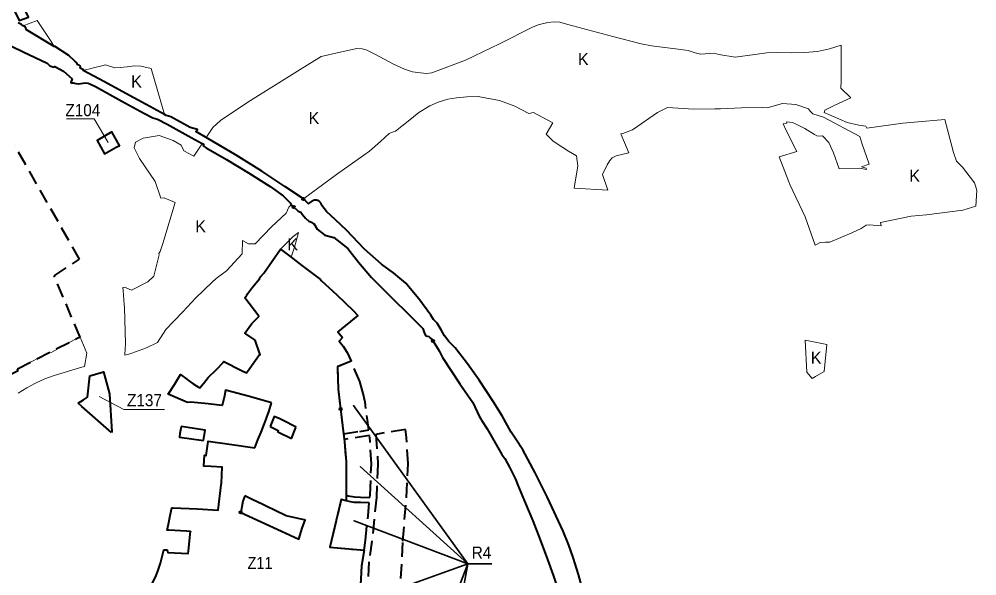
# Model space of a CAD drawing. Extents: x -650276 to -642489, y -1074311 to -1066658.
# Drawn here: x -646145 to -644241, y -1069915 to -1068808 of the extents above; entities that cross this region are included whole.
import ezdxf

# ---------------------------------------------------------------- set-up
doc = ezdxf.new("R2010")
doc.units = 0
doc.header["$LTSCALE"] = 9.6
doc.header["$PDMODE"] = 32
doc.header["$PDSIZE"] = 4.8
doc.linetypes.add('MEDIUM_DASHED', pattern=[4.5, 3, -1.5])
for name, color, linetype, lineweight in [('4', 7, 'Continuous', 40), ('44', 7, 'Continuous', 40), ('45', 7, 'Continuous', 40), ('46', 7, 'Continuous', 13), ('47', 7, 'Continuous', 13), ('48', 7, 'Continuous', 35), ('57', 7, 'Continuous', 35), ('59', 7, 'Continuous', 13), ('61', 7, 'MEDIUM_DASHED', 40), ('62', 7, 'Continuous', 35)]:
    doc.layers.add(name, color=color, linetype=linetype, lineweight=lineweight)

msp = doc.modelspace()

# ---------------------------------------------------------------- linework, layer by layer
at = {"layer": '4'}
for points in [[(-646004.7, -1069517.16), (-645977.73, -1069509.11), (-645965.36, -1069552.99), (-645960.78, -1069628.91), (-645961.36, -1069630.05)], [(-646027.49, -1069571.79), (-646017.39, -1069564.94), (-646009.52, -1069559.6), (-646004.7, -1069517.16)], [(-645961.36, -1069630.05), (-646020.4, -1069578.04), (-646027.49, -1069571.79)]]:
    msp.add_lwpolyline(points, dxfattribs=at)
at = {"layer": '44'}
for points in [[(-646305.678, -1068613.404), (-646243.997, -1068647.407), (-646236.707, -1068651.891), (-646228.691, -1068658.051), (-646221.348, -1068665.144), (-646213.659, -1068674.696), (-646209.179, -1068681.795), (-646204.654, -1068690.937), (-646145.083, -1068810.83), (-646126.317, -1068803.654), (-646186.371, -1068682.825)], [(-645579.94, -1069165.52), (-645616.63, -1069140.8), (-645662.44, -1069109.89), (-645713.61, -1069078.06), (-645770.04, -1069045.34), (-645773.38, -1069043.46), (-645793.638, -1069031.021), (-645790.53, -1069027.19), (-645805.16, -1069023.52), (-645843.56, -1069002.41), (-645848.18, -1069000.48), (-645852.91, -1068999.62), (-645856.26, -1068997.79), (-645892.77, -1068977.86), (-645933.28, -1068955.74), (-645975.31, -1068932.8), (-646017.55, -1068909.75), (-646017.39, -1068908.42), (-646023.56, -1068905.05), (-646023.13, -1068903.12), (-646023.92, -1068900.73), (-646025.57, -1068899.39), (-646028.18, -1068898.89), (-646031.31, -1068894.32), (-646034.65, -1068891.12), (-646046.48, -1068879.92), (-646074.78, -1068861.51), (-646075.56, -1068861.95), (-646130.68, -1068829.21), (-646132.62, -1068823.54), (-646136.99, -1068820.88), (-646140.73, -1068818.61), (-646146.85, -1068814.88)], [(-646182.57, -1068851.3), (-646137.23, -1068872.6), (-646089.63, -1068895.5), (-646084.1, -1068900.51), (-646076.09, -1068903.48), (-646074.51, -1068901.9), (-646057.13, -1068911.62), (-646039.84, -1068926.67), (-646042.5, -1068933.91), (-646040.65, -1068934.59), (-646037.5, -1068934.7), (-646032.61, -1068936.1)], [(-646032.61, -1068936.1), (-646027.69, -1068936.6), (-646022.77, -1068936.12), (-646017.6, -1068934.89), (-646012.64, -1068934.34), (-646007.7, -1068935.18), (-646002.95, -1068936.95), (-645993.5, -1068942.1), (-645940.77, -1068970.74), (-645896.91, -1068994.75), (-645879.17, -1069004.02), (-645874.49, -1069005.73), (-645869.83, -1069006.45), (-645850.79, -1069016.84), (-645803.29, -1069042.92), (-645781.12, -1069055.29), (-645777.73, -1069057.2), (-645779.49, -1069059.92), (-645773.29, -1069063.99), (-645732.65, -1069086.82), (-645688.87, -1069113.44), (-645646.08, -1069140.37), (-645620.2, -1069159.26), (-645606.11, -1069172.98), (-645603.91, -1069176.86), (-645599, -1069181.48)], [(-645571.9, -1069173.43), (-645579.94, -1069165.52), (-645579.94, -1069165.52)], [(-645543.43, -1069178.39), (-645543.547, -1069177.727), (-645543.706, -1069177.053), (-645543.907, -1069176.37), (-645544.154, -1069175.682), (-645544.448, -1069174.993), (-645544.792, -1069174.308), (-645545.186, -1069173.63), (-645545.631, -1069172.966), (-645546.127, -1069172.32), (-645546.674, -1069171.699), (-645547.269, -1069171.107), (-645547.91, -1069170.551), (-645548.594, -1069170.034), (-645549.317, -1069169.563), (-645550.076, -1069169.141), (-645550.863, -1069168.772), (-645551.674, -1069168.459), (-645552.504, -1069168.203), (-645553.344, -1069168.007), (-645554.191, -1069167.87), (-645555.036, -1069167.793), (-645555.875, -1069167.772), (-645556.702, -1069167.808), (-645557.511, -1069167.896), (-645558.298, -1069168.035), (-645559.06, -1069168.219), (-645559.793, -1069168.445), (-645560.494, -1069168.709), (-645561.162, -1069169.007), (-645561.794, -1069169.334), (-645562.39, -1069169.686), (-645562.95, -1069170.06), (-645567.5, -1069173.46), (-645569.81, -1069175.03), (-645571.9, -1069173.43)], [(-645599, -1069181.48), (-645599, -1069181.48), (-645592.24, -1069187.73), (-645590.41, -1069189.45), (-645584.73, -1069191.88), (-645582.63, -1069195.88), (-645575.58, -1069203.57), (-645568.9, -1069209.87), (-645567.07, -1069210.45), (-645562.17, -1069212.02), (-645560.72, -1069214.25), (-645559.33, -1069214.54), (-645552.2, -1069225.59), (-645537.44, -1069237.41), (-645519.59, -1069242.38), (-645491.63, -1069264.25), (-645470.44, -1069291.24), (-645444.62, -1069321.35), (-645405.7, -1069360.27), (-645368.13, -1069397.37), (-645358.04, -1069406.84), (-645342.49, -1069423.06), (-645339.31, -1069433.27), (-645336.66, -1069437.47), (-645330.57, -1069438.89), (-645327.2, -1069442.53), (-645323.36, -1069445.79), (-645322.13, -1069447.96)], [(-645024.45, -1069944.43), (-645032.85, -1069912.07), (-645043.5, -1069878.37), (-645051.78, -1069854.2), (-645063.26, -1069825.99), (-645095.1, -1069757.62), (-645118.98, -1069710.08), (-645143.56, -1069664.05), (-645148.8, -1069656.1), (-645150.3, -1069653.84), (-645153.33, -1069649.24), (-645166.67, -1069629), (-645184.88, -1069596.58), (-645202.56, -1069568.23), (-645230.1, -1069525.98), (-645253.4, -1069493.06), (-645278.31, -1069461.33), (-645281.4, -1069458.4), (-645290.5, -1069449.03), (-645299.61, -1069437.97), (-645306.16, -1069425.55), (-645314.14, -1069412.54), (-645321.1, -1069405.21), (-645326.59, -1069396.64), (-645350.63, -1069363.98), (-645371.12, -1069339.47), (-645376.38, -1069332.65), (-645400.07, -1069313.32), (-645424.8, -1069295.24), (-645458.45, -1069265.56), (-645494.13, -1069227.63), (-645515.89, -1069206.66), (-645534.25, -1069190.56), (-645543.43, -1069178.39)], [(-645322.13, -1069447.96), (-645309.62, -1069467.79), (-645303.57, -1069480.49), (-645268.57, -1069533.23), (-645242.75, -1069570.26), (-645230.42, -1069597.39), (-645227.27, -1069602.68), (-645225.7, -1069605.32), (-645214.76, -1069622.37), (-645198.41, -1069650.49), (-645185.17, -1069673.38), (-645179.12, -1069681.3), (-645170.3, -1069698.91), (-645158.43, -1069722.61), (-645153.44, -1069734.71), (-645140.27, -1069766.68), (-645123.84, -1069805.38), (-645108.74, -1069843.58), (-645094.42, -1069882.65), (-645083.31, -1069913.37), (-645071.53, -1069948.89)]]:
    msp.add_lwpolyline(points, dxfattribs=at)
for p in [(-645579.94, -1069165.52), (-645599, -1069181.48), (-645322.13, -1069447.96)]:
    msp.add_point(p, dxfattribs=at)
at = {"layer": '45'}
msp.add_line((-645704.355, -1069788.786), (-645623.75, -1069825.97), dxfattribs=at)
for points in [[(-645944.69, -1069060.7), (-645960.67, -1069032.26), (-645990.13, -1069049.3), (-645975.48, -1069075.71), (-645952.21, -1069062.4)], [(-645944.69, -1069060.7), (-645960.67, -1069032.26), (-645990.13, -1069049.3), (-645975.48, -1069075.71), (-645952.21, -1069062.4)], [(-645952.21, -1069062.4), (-645946.84, -1069059.58), (-645944.69, -1069060.7)], [(-645952.21, -1069062.4), (-645946.84, -1069059.58), (-645944.69, -1069060.7)], [(-645668.722, -1069398.75), (-645696.19, -1069362.01), (-645692.38, -1069356.67), (-645690.81, -1069354.28), (-645687.22, -1069349), (-645680.8, -1069341.08), (-645667, -1069324.06), (-645664.89, -1069320.2), (-645658.9, -1069312.83), (-645625.11, -1069265.42), (-645604.114, -1069281.49), (-645594.94, -1069288.511)], [(-645594.94, -1069288.511), (-645583.13, -1069297.55), (-645546.19, -1069325.81), (-645544.26, -1069327.35), (-645513.41, -1069356.18), (-645480.72, -1069386.96), (-645471.738, -1069397.026), (-645511.464, -1069429.794), (-645501.878, -1069440.838)], [(-645675.91, -1069446.56), (-645694.21, -1069433.78), (-645696.45, -1069432.21), (-645682.28, -1069412.88), (-645678.06, -1069408.54), (-645668.61, -1069398.9), (-645668.722, -1069398.75)], [(-645501.878, -1069440.838), (-645508.994, -1069447.955), (-645501, -1069458), (-645493, -1069471), (-645484.783, -1069488.256), (-645512, -1069499), (-645511, -1069544), (-645506, -1069583)], [(-645786.388, -1069541.673), (-645779.376, -1069532.962), (-645778.754, -1069532.198), (-645769.369, -1069520.672), (-645768.995, -1069520.305), (-645752.715, -1069504.328), (-645738.986, -1069489.868), (-645737.897, -1069488.534), (-645702.82, -1069506.64), (-645692.87, -1069511.229), (-645690.84, -1069508.32), (-645667.31, -1069474.6), (-645665.58, -1069475.61), (-645675.91, -1069446.56)], [(-645836.44, -1069534.5), (-645824.05, -1069514.34), (-645811.75, -1069523.81), (-645808.1, -1069526.61), (-645799.07, -1069532.8), (-645790.62, -1069538.59), (-645786.388, -1069541.673)], [(-645810.08, -1069570.39), (-645848.78, -1069553.91), (-645836.44, -1069534.5)], [(-645643.16, -1069570.6), (-645687.29, -1069558.04), (-645734.5, -1069545.89), (-645736.8, -1069556.91), (-645741.14, -1069576.19), (-645769.04, -1069573), (-645803.513, -1069569.263), (-645810.08, -1069570.39)], [(-645676.34, -1069660.28), (-645670.23, -1069644.67), (-645664.19, -1069629.24), (-645657.52, -1069612.2), (-645656.15, -1069608.71), (-645649.91, -1069592.39), (-645648.68, -1069589.06), (-645644.56, -1069575.61), (-645643.16, -1069570.6)], [(-645506, -1069583), (-645500.137, -1069632.833), (-645500.137, -1069632.833)], [(-645594.58, -1069619.56), (-645621.56, -1069605.68), (-645626.95, -1069602.91), (-645638.203, -1069597.8), (-645645.715, -1069618.085)], [(-645823.082, -1069618.279), (-645823.13, -1069618.452), (-645825.295, -1069632.053), (-645826.133, -1069638.843), (-645826.151, -1069639.057), (-645778.45, -1069645.92)], [(-645823.082, -1069618.279), (-645823.13, -1069618.452), (-645825.295, -1069632.053), (-645826.133, -1069638.843), (-645826.151, -1069639.057), (-645778.45, -1069645.92)], [(-645778.45, -1069645.92), (-645775.46, -1069625.13), (-645823.082, -1069618.279)], [(-645778.45, -1069645.92), (-645775.46, -1069625.13), (-645823.082, -1069618.279)], [(-645645.715, -1069618.085), (-645629.78, -1069626.03), (-645630.93, -1069628.84), (-645603.7, -1069641.75)], [(-645603.7, -1069641.75), (-645594.818, -1069620.139), (-645594.58, -1069619.56)], [(-645839.721, -1069780.247), (-645839.658, -1069779.835), (-645791.2, -1069781.92), (-645749.48, -1069784.61), (-645743.36, -1069733.7), (-645743.01, -1069730.72), (-645741.43, -1069698.68), (-645763.24, -1069697.58), (-645777.62, -1069696.85), (-645776.45, -1069675.26), (-645773.02, -1069675.47), (-645769.36, -1069648), (-645769.264, -1069647.213), (-645726.57, -1069653.22), (-645676.34, -1069660.28)], [(-645500.137, -1069632.833), (-645498, -1069648), (-645495, -1069688), (-645495, -1069744), (-645495, -1069766), (-645504.976, -1069763.332), (-645527, -1069858), (-645459.312, -1069864.01), (-645464.288, -1069895.362), (-645465.756, -1069921.035), (-645469.701, -1069990.011)], [(-645696.517, -1069756.039), (-645700.028, -1069766.286), (-645704.355, -1069788.786)], [(-645660.57, -1069773.31), (-645681.76, -1069763.13), (-645696.517, -1069756.039)], [(-645804.185, -1069825.84), (-645804.28, -1069826.76), (-645812.18, -1069826.3), (-645847.62, -1069824.26), (-645850.63, -1069824.09), (-645848.35, -1069812.09), (-645844.57, -1069795.07), (-645841.41, -1069779.76), (-645839.658, -1069779.835), (-645839.721, -1069780.247)], [(-645613.84, -1069795.78), (-645635.79, -1069785.23), (-645652.378, -1069777.251), (-645660.57, -1069773.31)], [(-645623.75, -1069825.97), (-645589.23, -1069841.89), (-645582.31, -1069820.05), (-645577.52, -1069807.26), (-645576.34, -1069804.13), (-645578.134, -1069803.731), (-645613.84, -1069795.78)], [(-645742.967, -1069941.862), (-645768.424, -1069948.431), (-645833, -1069966), (-645880.431, -1069930.3), (-645874.219, -1069917.496), (-645869.262, -1069905.935), (-645863.95, -1069889.468), (-645857.289, -1069863.338), (-645857.204, -1069862.954), (-645850.92, -1069863.41), (-645849.79, -1069868.4), (-645808.84, -1069870.75), (-645808.28, -1069865.39), (-645804.185, -1069825.84)]]:
    msp.add_lwpolyline(points, dxfattribs=at)
for p in [(-645506, -1069583), (-645704.355, -1069788.786)]:
    msp.add_point(p, dxfattribs=at)
at = {"layer": '46'}
msp.add_lwpolyline([(-646051.21, -1069006.26), (-645996.286, -1069006.26), (-645968.211, -1069053.466)], dxfattribs=at)
msp.add_lwpolyline([(-646051.21, -1069006.26), (-645996.286, -1069006.26), (-645968.211, -1069053.466)], dxfattribs=at)
at = {"layer": '47'}
for points in [[(-646075.56, -1068861.95), (-646130.68, -1068829.21), (-646132.62, -1068823.54), (-646136.99, -1068820.88), (-646109.35, -1068810.23)], [(-646109.35, -1068810.23), (-646081.72, -1068852.51), (-646075.56, -1068861.95)], [(-645239.85, -1068880.94), (-645190.22, -1068857.23), (-645124.36, -1068824.11), (-645112.77, -1068819.13), (-645093.56, -1068814.27), (-645081.12, -1068813.15), (-645070.05, -1068814), (-645053.97, -1068818.31), (-644964.45, -1068842.38), (-644908.26, -1068856.91), (-644887.91, -1068860.82), (-644834.84, -1068867.4), (-644814.47, -1068870.12), (-644800.87, -1068874.97), (-644790.41, -1068877.73), (-644763.04, -1068875.63), (-644753.71, -1068878.41), (-644721.29, -1068883.2), (-644681.99, -1068878.15), (-644658.39, -1068874.59), (-644636.55, -1068874.02), (-644608.71, -1068874.78), (-644583.26, -1068874.26), (-644557.75, -1068872.33), (-644533.84, -1068867.2), (-644510.62, -1068859.35), (-644510.567, -1068897.909), (-644510.75, -1068931.16), (-644511.47, -1068945.37), (-644491.31, -1068964.35), (-644523.4, -1068978.98), (-644543.05, -1068988.64), (-644544.02, -1068993.75), (-644498.28, -1069013.19), (-644475.09, -1069018.99), (-644461.74, -1069020.83), (-644459.67, -1069024.41), (-644387.91, -1069014.64), (-644364.53, -1069012.83), (-644304.6, -1069007.55), (-644286.94, -1069073.19)], [(-645544.33, -1068882.17), (-645500.83, -1068872.25), (-645473.89, -1068866.13), (-645462.97, -1068866.88), (-645455.34, -1068868.9), (-645436.72, -1068877.85), (-645400.92, -1068897.18), (-645379.06, -1068907.27), (-645362.84, -1068912.83), (-645352.46, -1068914.25), (-645335.45, -1068915.77)], [(-645426.3, -1069051.02), (-645448.49, -1069070.45), (-645459.5, -1069078.59), (-645514.08, -1069116.5), (-645579.94, -1069165.52), (-645616.63, -1069140.8), (-645662.44, -1069109.89), (-645694.447, -1069089.98), (-645713.61, -1069078.06), (-645770.04, -1069045.34), (-645773.38, -1069043.46), (-645760.07, -1069023.11), (-645744.65, -1069009.71), (-645690.34, -1068973.16), (-645586.28, -1068907.71), (-645544.33, -1068882.17)], [(-645335.45, -1068915.77), (-645324.79, -1068914.82), (-645257.5, -1068889.68), (-645239.85, -1068880.94)], [(-645973.36, -1068898.93), (-645980.93, -1068900.85), (-645994.9, -1068904.1), (-646004.88, -1068906.5), (-646010.48, -1068907.86), (-646017.55, -1068909.75), (-645975.31, -1068932.8), (-645933.28, -1068955.74)], [(-645882.63, -1068905.88), (-645902.91, -1068901.43), (-645915.61, -1068901.02), (-645930.1, -1068902.47), (-645944.23, -1068904.13), (-645954.59, -1068904.41), (-645973.36, -1068898.93)], [(-645933.28, -1068955.74), (-645892.77, -1068977.86), (-645856.26, -1068997.79), (-645882.63, -1068905.88)], [(-645131.73, -1068995.69), (-645159.37, -1068981.11), (-645189.84, -1068969.91), (-645229.27, -1068962.28), (-645232.4, -1068961.67), (-645255.21, -1068962.49), (-645275.45, -1068964.38), (-645292.77, -1068966.91), (-645311.99, -1068972.74), (-645328.55, -1068980.37), (-645350.17, -1068993.33), (-645371.35, -1069010.64), (-645396.53, -1069030.88)], [(-644473.222, -1069040.994), (-644545.54, -1069003.12), (-644567.09, -1068996.26), (-644572.05, -1068991.08), (-644575.29, -1068986.48), (-644600.67, -1068977.77), (-644627.41, -1068975.6), (-644657.61, -1068983.91), (-644667.57, -1068983.47), (-644708.6, -1068984.54), (-644750.67, -1068986.34), (-644761.88, -1068986.27), (-644803.31, -1068986.97), (-644855.56, -1068983.38), (-644875.57, -1068993.47), (-644925.35, -1069027.75), (-644944.9, -1069035.04), (-644948.575, -1069035.675)], [(-644948.575, -1069035.675), (-644941.27, -1069052.9), (-644932.95, -1069073.65), (-644958.25, -1069079.99), (-644965.95, -1069083.67), (-644970.84, -1069088.8), (-644975.56, -1069097.564), (-644985.15, -1069116.67), (-644974.34, -1069147.85), (-645041.751, -1069143.816), (-645034.13, -1069099.79), (-645036.87, -1069079.78), (-645052.83, -1069070.4), (-645075.206, -1069055.523), (-645084.19, -1069049.55), (-645096.97, -1069036.63), (-645084.17, -1069013.922), (-645122.25, -1068993.21), (-645131.73, -1068995.69)], [(-644286.94, -1069073.19), (-644281.26, -1069090.19), (-644269.11, -1069102.31), (-644245.65, -1069133.66), (-644243.14, -1069139.47), (-644240.67, -1069148.58), (-644242.48, -1069179.49), (-644268.7, -1069187.42), (-644340.83, -1069197.13), (-644371.08, -1069199.84), (-644432.53, -1069212.02), (-644430.91, -1069218.82), (-644454.87, -1069217.05), (-644460.97, -1069217.61), (-644470.64, -1069224), (-644489.27, -1069233.04), (-644532.71, -1069251.12), (-644541.83, -1069251.66), (-644552.01, -1069252.24), (-644562.47, -1069257.56), (-644582.29, -1069201.27), (-644612.3, -1069136.45), (-644614.41, -1069131.08), (-644633.66, -1069082), (-644598.81, -1069071.02), (-644619.54, -1069029.55), (-644625.69, -1069015.84), (-644618.8, -1069014.7), (-644619.1, -1069011.81), (-644607.16, -1069013.56), (-644601.43, -1069015.74), (-644583.05, -1069025.29), (-644563.19, -1069037.21), (-644558.56, -1069039.86), (-644553.62, -1069040.53), (-644547.31, -1069040.11), (-644535.13, -1069053.18), (-644525.83, -1069073.84), (-644514.47, -1069105.62), (-644474.33, -1069104.22), (-644459.82, -1069106.73), (-644461.01, -1069104.36), (-644470.37, -1069101.55), (-644454.75, -1069096.51), (-644469.28, -1069054.8), (-644473.222, -1069040.994)], [(-645797.957, -1069080.052), (-645817.59, -1069069.6), (-645822.85, -1069058.8), (-645838.99, -1069049.31), (-645866.69, -1069039.37), (-645898.57, -1069044.24), (-645913.8, -1069052.51), (-645916.2, -1069063.8), (-645905.94, -1069085.11), (-645874.98, -1069131.01), (-645863.38, -1069163.79), (-645856.76, -1069163.17), (-645835.157, -1069172.184)], [(-645396.53, -1069030.88), (-645405.02, -1069033.34), (-645409.61, -1069035.17), (-645426.3, -1069051.02)], [(-645938.399, -1069347.452), (-645936.046, -1069375.651), (-645935.58, -1069381.24), (-645933.97, -1069453.52), (-645934.8, -1069474.71), (-645935.05, -1069476.32), (-645928.99, -1069474.55), (-645921.13, -1069472.25), (-645892.03, -1069461.43), (-645869.91, -1069451.02), (-645853.28, -1069425.27), (-645838.17, -1069409.28), (-645819.62, -1069389.66), (-645793.63, -1069362.15), (-645761.411, -1069331.17), (-645753.58, -1069323.64), (-645733.1, -1069308.58), (-645701.62, -1069274.36), (-645701.33, -1069247.86), (-645689, -1069254.5), (-645675.82, -1069254.48), (-645643.34, -1069220.59), (-645613.9, -1069193.45), (-645608.71, -1069181.51), (-645603.91, -1069176.86), (-645606.11, -1069172.98), (-645620.2, -1069159.26), (-645646.08, -1069140.37), (-645688.87, -1069113.44), (-645732.65, -1069086.82), (-645773.29, -1069063.99), (-645779.49, -1069059.92), (-645777.73, -1069057.2), (-645781.12, -1069055.29), (-645784.69, -1069060.74), (-645797.957, -1069080.052)], [(-645835.157, -1069172.184), (-645859.43, -1069254.08), (-645864.96, -1069269.78), (-645867.42, -1069274.21), (-645866.45, -1069276.32), (-645877.15, -1069319.06), (-645877.15, -1069319.06), (-645889.29, -1069330.52), (-645921.56, -1069346.6), (-645935.33, -1069340.64), (-645938.89, -1069341.56), (-645938.399, -1069347.452)], [(-645604.114, -1069281.49), (-645597.738, -1069261.522), (-645589.844, -1069231.908), (-645600.55, -1069239.93), (-645625.11, -1069265.42)], [(-645625.11, -1069265.42), (-645625.11, -1069265.42), (-645604.114, -1069281.49)], [(-646023.96, -1069440.34), (-646028.16, -1069441.58), (-646080.35, -1069469.89), (-646102.15, -1069479.49), (-646148.5, -1069503), (-646146.8, -1069506.6), (-646189.17, -1069528.74), (-646209.9, -1069538.5), (-646321.973, -1069686.855), (-646554.262, -1069762.602), (-646581.489, -1069759.421), (-646585.51, -1069769.57)], [(-646017.63, -1069499.08), (-646017.63, -1069499.08), (-646015.16, -1069498.74), (-646010.65, -1069471.91), (-646023.96, -1069440.34)], [(-646146.81, -1069551.97), (-646129.87, -1069541.19), (-646112.56, -1069531.78), (-646094.39, -1069523.34), (-646075.48, -1069516.38), (-646020.75, -1069500), (-646017.63, -1069499.08)]]:
    msp.add_lwpolyline(points, dxfattribs=at)
msp.add_lwpolyline([(-644578.92, -1069446.8), (-644581.87, -1069446.28), (-644579.047, -1069509.608), (-644567.976, -1069522.752), (-644561.24, -1069518.27), (-644543.99, -1069508.88), (-644539, -1069454.88)], close=True, dxfattribs=at)
at = {"layer": '57'}
msp.add_line((-645253.165, -1069890.903), (-645205.454, -1069890.903), dxfattribs=at)
at = {"layer": '59'}
msp.add_lwpolyline([(-645856.191, -1069584.407), (-645937.111, -1069584.407), (-645985.786, -1069558.403)], dxfattribs=at)
at = {"layer": '61'}
msp.add_lwpolyline([(-646583.457, -1069759.191), (-646554.262, -1069762.602), (-646321.973, -1069686.855), (-646209.9, -1069538.5), (-646146.8, -1069506.6), (-646148.5, -1069503), (-646028.16, -1069441.58), (-646023.96, -1069440.34), (-646075.49, -1069318.19), (-646025.14, -1069285.394), (-646153.307, -1069059.947)], dxfattribs=at)
for points in [[(-645506, -1069583), (-645500.137, -1069632.833), (-645468, -1069627.622), (-645450.05, -1069624.711), (-645457.223, -1069569.632), (-645461.32, -1069552.039), (-645467.477, -1069528.79), (-645484.783, -1069488.256), (-645512, -1069499), (-645511, -1069544)], [(-645374.642, -1069640.059), (-645376.605, -1069623.944), (-645435.877, -1069633.555), (-645431.642, -1069692.811), (-645434.826, -1069759.235), (-645443.679, -1069846.142), (-645449.445, -1069887.328), (-645455.84, -1069992.731), (-645379.881, -1070001.766), (-645385.95, -1069920.347), (-645382.14, -1069845.883), (-645378.587, -1069802.788), (-645374.542, -1069758.923), (-645371.563, -1069692.39)], [(-645495, -1069688), (-645495, -1069744), (-645495, -1069754.815), (-645491, -1069756), (-645478, -1069758), (-645466.517, -1069758.328), (-645447.852, -1069758.862), (-645447.398, -1069753.935), (-645444.664, -1069692.902), (-645447.387, -1069646.623), (-645448.725, -1069635.639), (-645498.61, -1069643.729), (-645498, -1069648)], [(-645504.976, -1069763.332), (-645527, -1069858), (-645464.93, -1069863.477), (-645459.312, -1069864.01), (-645456.586, -1069844.534), (-645451.227, -1069795.473), (-645448.864, -1069769.837), (-645466.353, -1069769.337), (-645478.997, -1069768.976), (-645482.753, -1069768.26), (-645495, -1069766)]]:
    msp.add_lwpolyline(points, close=True, dxfattribs=at)
at = {"layer": '62'}
msp.add_line((-645253.165, -1069890.903), (-645338.143, -1070356.741), dxfattribs=at)
msp.add_lwpolyline([(-645205.454, -1069890.903), (-645253.165, -1069890.903), (-645480.406, -1069576.285), (-645253.165, -1069890.903), (-645466.774, -1069697.69), (-645253.165, -1069890.903), (-645479.043, -1069805.455), (-645253.165, -1069890.903), (-645420.426, -1069951.415), (-645253.165, -1069890.903), (-645348.178, -1070139.662)], dxfattribs=at)

# ---------------------------------------------------------------- texts
at = {"layer": '45', "width": 0.9}
msp.add_text('Z11', height=24, dxfattribs=at).set_placement((-645690.933, -1069901.172))
at = {"layer": '46', "width": 0.95}
msp.add_text('Z104', height=24, dxfattribs=at).set_placement((-646053.286, -1069000.877))
msp.add_text('Z104', height=24, dxfattribs=at).set_placement((-646053.286, -1069000.877))
at = {"layer": '48'}
for p in [(-645034.002, -1068899.33), (-645922.543, -1068943.866), (-645922.543, -1068943.866), (-645569.606, -1069016.557), (-645569.606, -1069016.557), (-644374.971, -1069131.317), (-645795.003, -1069231.861), (-645795.003, -1069231.861), (-645611.977, -1069267.447), (-644570.824, -1069493.226), (-644570.824, -1069493.226)]:
    msp.add_text('K', height=24, dxfattribs=at).set_placement(p)
at = {"layer": '59', "width": 0.95}
msp.add_text('Z137', height=24, dxfattribs=at).set_placement((-645930.722, -1069577.643))
at = {"layer": '62', "width": 0.95}
msp.add_text('R4', height=24, dxfattribs=at).set_placement((-645245.139, -1069880.683))

doc.saveas('drawing.dxf')
